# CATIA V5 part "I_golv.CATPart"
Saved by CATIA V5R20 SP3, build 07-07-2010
Part number: Part1
Bounding box of the stored display mesh (mm): x -5000 to 3000, y -2500 to 2500, z -20 to 0
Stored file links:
  Y:\A1_LAB_INTRO_2011\LAB_INTRO_DATA_2011\I_golv.CATPart
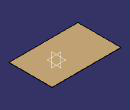
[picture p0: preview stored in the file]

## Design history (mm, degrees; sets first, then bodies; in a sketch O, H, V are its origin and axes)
Body1 (main body)
  Sketch1 on xy-plane, origin (0, 0, 0), H (1, 0, 0), V (0, 1, 0)
    line L1 (-5000, -2500) -> (3000, -2500)
    line L2 (3000, -2500) -> (3000, 2500)
    line L3 (3000, 2500) -> (-5000, 2500)
    line L4 (-5000, 2500) -> (-5000, -2500)
    horizontal: L1 H, L3 H
    vertical: L2 V, L4 V
  Pad1: profile Sketch1, direction (0, 0, -1), length 20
